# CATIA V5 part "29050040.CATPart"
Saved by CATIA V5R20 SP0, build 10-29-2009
Part number: 29050040
Definition: NONE
Nomenclature: 29050040
Source: Unknown
Description: 29050040
Bounding box of the stored display mesh (mm): x -20 to 44.548, y -39 to 73.548, z -29 to 29
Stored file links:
  C:\Users\Utente\Desktop\IO LAVORO\3D X SITO CF\X SITO\PLASTICA\RF1\29050040.CATPart
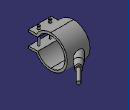
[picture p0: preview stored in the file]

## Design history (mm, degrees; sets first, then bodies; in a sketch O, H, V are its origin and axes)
Body1 "29050040" (main body)
  Solid1: solid without history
